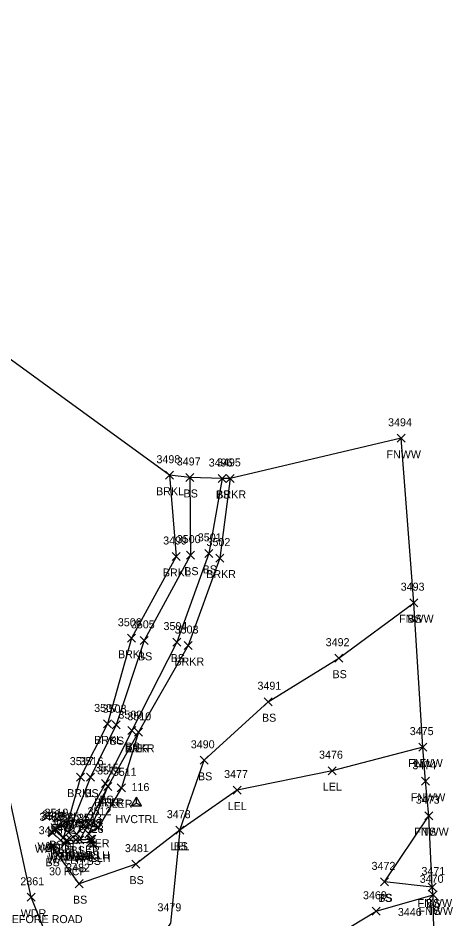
# Model space of a CAD drawing. Extents: x 1650221 to 1650634, y 244606 to 249996.
# Drawn here: x 1650356.4 to 1650465, y 246819.2 to 247044.4 of the extents above; entities that cross this region are included whole.
import ezdxf

# ---------------------------------------------------------------- set-up
doc = ezdxf.new("R2010")
doc.units = 0
for name, color, linetype in [('C_A', 7, 'Continuous'), ('C_I', 7, 'Continuous'), ('CPSM', 7, 'Continuous'), ('D_A', 7, 'Continuous'), ('D_C', 7, 'Continuous'), ('D_I', 7, 'Continuous'), ('D_TIC', 7, 'Continuous'), ('DHW', 7, 'Continuous'), ('L_A', 7, 'Continuous'), ('L_I', 7, 'Continuous'), ('L_TIC', 7, 'Continuous'), ('LARO', 7, 'Continuous'), ('LAWA', 7, 'Continuous'), ('LAWE', 7, 'Continuous'), ('LELB', 7, 'Continuous'), ('LFNC', 7, 'Continuous'), ('LSOGP', 7, 'Continuous'), ('S_C', 7, 'Continuous')]:
    doc.layers.add(name, color=color, linetype=linetype)

msp = doc.modelspace()

# ---------------------------------------------------------------- linework, layer by layer
at = {"layer": 'CPSM'}
for p, q in [((1650384.74, 246847.47), (1650385.99, 246849.64)), ((1650387.24, 246847.47), (1650385.99, 246849.64)), ((1650385.99, 246848.19), (1650385.99, 246849.64)), ((1650384.74, 246847.47), (1650385.99, 246848.19)), ((1650384.74, 246847.47), (1650387.24, 246847.47)), ((1650385.99, 246848.19), (1650385.99, 246848.19)), ((1650385.99, 246848.19), (1650387.24, 246847.47))]:
    msp.add_line(p, q, dxfattribs=at)
at = {"layer": 'D_TIC'}
for points in [[(1650363.97, 246839.77), (1650365.97, 246841.77)], [(1650365.97, 246839.77), (1650363.97, 246841.77)], [(1650364.66, 246840.35), (1650366.66, 246842.35)], [(1650366.66, 246840.35), (1650364.66, 246842.35)], [(1650364.66, 246840.35), (1650366.66, 246842.35)], [(1650366.66, 246840.35), (1650364.66, 246842.35)], [(1650368.48, 246838.15), (1650370.48, 246840.15)], [(1650370.48, 246838.15), (1650368.48, 246840.15)], [(1650373.5, 246838.15), (1650375.5, 246840.15)], [(1650375.5, 246838.15), (1650373.5, 246840.15)], [(1650367.03, 246837.03), (1650369.03, 246839.03)], [(1650369.03, 246837.03), (1650367.03, 246839.03)], [(1650367.35, 246837.78), (1650369.35, 246839.78)], [(1650369.35, 246837.78), (1650367.35, 246839.78)], [(1650367.35, 246837.78), (1650369.35, 246839.78)], [(1650369.35, 246837.78), (1650367.35, 246839.78)], [(1650373.65, 246837.49), (1650375.65, 246839.49)], [(1650375.65, 246837.49), (1650373.65, 246839.49)]]:
    msp.add_lwpolyline(points, dxfattribs=at)
at = {"layer": 'DHW'}
for points in [[(1650365.66, 246841.35), (1650364.97, 246840.77), (1650368.03, 246838.03), (1650374.65, 246838.49), (1650374.5, 246839.15), (1650368.35, 246838.78)], [(1650365.66, 246841.35), (1650368.35, 246838.78)]]:
    msp.add_lwpolyline(points, dxfattribs=at)
at = {"layer": 'L_TIC'}
for points in [[(1650451.05, 246938.34), (1650453.05, 246940.34)], [(1650453.05, 246938.34), (1650451.05, 246940.34)], [(1650393.2, 246929.11), (1650395.2, 246931.11)], [(1650395.2, 246929.11), (1650393.2, 246931.11)], [(1650398.27, 246928.56), (1650400.27, 246930.56)], [(1650400.27, 246928.56), (1650398.27, 246930.56)], [(1650406.32, 246928.28), (1650408.32, 246930.28)], [(1650408.32, 246928.28), (1650406.32, 246930.28)], [(1650408.31, 246928.32), (1650410.31, 246930.32)], [(1650410.31, 246928.32), (1650408.31, 246930.32)], [(1650394.89, 246908.81), (1650396.89, 246910.81)], [(1650396.89, 246908.81), (1650394.89, 246910.81)], [(1650398.44, 246909.15), (1650400.44, 246911.15)], [(1650400.44, 246909.15), (1650398.44, 246911.15)], [(1650403.04, 246909.59), (1650405.04, 246911.59)], [(1650405.04, 246909.59), (1650403.04, 246911.59)], [(1650405.78, 246908.41), (1650407.78, 246910.41)], [(1650407.78, 246908.41), (1650405.78, 246910.41)], [(1650454.2, 246897.26), (1650456.2, 246899.26)], [(1650456.2, 246897.26), (1650454.2, 246899.26)], [(1650454.2, 246897.26), (1650456.2, 246899.26)], [(1650456.2, 246897.26), (1650454.2, 246899.26)], [(1650383.69, 246888.38), (1650385.69, 246890.38)], [(1650385.69, 246888.38), (1650383.69, 246890.38)], [(1650386.89, 246887.85), (1650388.89, 246889.85)], [(1650388.89, 246887.85), (1650386.89, 246889.85)], [(1650395.04, 246887.42), (1650397.04, 246889.42)], [(1650397.04, 246887.42), (1650395.04, 246889.42)], [(1650397.83, 246886.56), (1650399.83, 246888.56)], [(1650399.83, 246886.56), (1650397.83, 246888.56)], [(1650435.47, 246883.4), (1650437.47, 246885.4)], [(1650437.47, 246883.4), (1650435.47, 246885.4)], [(1650417.86, 246872.52), (1650419.86, 246874.52)], [(1650419.86, 246872.52), (1650417.86, 246874.52)], [(1650377.72, 246866.97), (1650379.72, 246868.97)], [(1650379.72, 246866.97), (1650377.72, 246868.97)], [(1650379.85, 246866.77), (1650381.85, 246868.77)], [(1650381.85, 246866.77), (1650379.85, 246868.77)], [(1650383.78, 246865.3), (1650385.78, 246867.3)], [(1650385.78, 246865.3), (1650383.78, 246867.3)], [(1650385.45, 246864.88), (1650387.45, 246866.88)], [(1650387.45, 246864.88), (1650385.45, 246866.88)], [(1650385.45, 246864.88), (1650387.45, 246866.88)], [(1650387.45, 246864.88), (1650385.45, 246866.88)], [(1650456.47, 246861.18), (1650458.47, 246863.18)], [(1650458.47, 246861.18), (1650456.47, 246863.18)], [(1650456.47, 246861.18), (1650458.47, 246863.18)], [(1650458.47, 246861.18), (1650456.47, 246863.18)], [(1650401.87, 246857.88), (1650403.87, 246859.88)], [(1650403.87, 246857.88), (1650401.87, 246859.88)], [(1650433.86, 246855.29), (1650435.86, 246857.29)], [(1650435.86, 246855.29), (1650433.86, 246857.29)], [(1650370.99, 246853.68), (1650372.99, 246855.68)], [(1650372.99, 246853.68), (1650370.99, 246855.68)], [(1650373.49, 246853.67), (1650375.49, 246855.67)], [(1650375.49, 246853.67), (1650373.49, 246855.67)], [(1650377.24, 246852.05), (1650379.24, 246854.05)], [(1650379.24, 246852.05), (1650377.24, 246854.05)], [(1650457.12, 246852.65), (1650459.12, 246854.65)], [(1650459.12, 246852.65), (1650457.12, 246854.65)], [(1650377.8, 246851.35), (1650379.8, 246853.35)], [(1650379.8, 246851.35), (1650377.8, 246853.35)], [(1650377.8, 246851.35), (1650379.8, 246853.35)], [(1650379.8, 246851.35), (1650377.8, 246853.35)], [(1650381.17, 246851.01), (1650383.17, 246853.01)], [(1650383.17, 246851.01), (1650381.17, 246853.01)], [(1650410.1, 246850.45), (1650412.1, 246852.45)], [(1650412.1, 246850.45), (1650410.1, 246852.45)], [(1650457.97, 246844.05), (1650459.97, 246846.05)], [(1650459.97, 246844.05), (1650457.97, 246846.05)], [(1650457.97, 246844.05), (1650459.97, 246846.05)], [(1650459.97, 246844.05), (1650457.97, 246846.05)], [(1650364.7, 246840.8), (1650366.7, 246842.8)], [(1650366.7, 246840.8), (1650364.7, 246842.8)], [(1650375.43, 246841.16), (1650377.43, 246843.16)], [(1650377.43, 246841.16), (1650375.43, 246843.16)], [(1650395.79, 246840.42), (1650397.79, 246842.42)], [(1650397.79, 246840.42), (1650395.79, 246842.42)], [(1650395.79, 246840.42), (1650397.79, 246842.42)], [(1650397.79, 246840.42), (1650395.79, 246842.42)], [(1650395.79, 246840.42), (1650397.79, 246842.42)], [(1650397.79, 246840.42), (1650395.79, 246842.42)], [(1650363.79, 246839.99), (1650365.79, 246841.99)], [(1650365.79, 246839.99), (1650363.79, 246841.99)], [(1650366.76, 246838.63), (1650368.76, 246840.63)], [(1650368.76, 246838.63), (1650366.76, 246840.63)], [(1650366.76, 246838.63), (1650368.76, 246840.63)], [(1650368.76, 246838.63), (1650366.76, 246840.63)], [(1650367.96, 246839.82), (1650369.96, 246841.82)], [(1650369.96, 246839.82), (1650367.96, 246841.82)], [(1650367.96, 246839.82), (1650369.96, 246841.82)], [(1650369.96, 246839.82), (1650367.96, 246841.82)], [(1650370.07, 246839.39), (1650372.07, 246841.39)], [(1650372.07, 246839.39), (1650370.07, 246841.39)], [(1650373.03, 246839.52), (1650375.03, 246841.52)], [(1650375.03, 246839.52), (1650373.03, 246841.52)], [(1650373.76, 246838.22), (1650375.76, 246840.22)], [(1650375.76, 246838.22), (1650373.76, 246840.22)], [(1650363.79, 246836.41), (1650365.79, 246838.41)], [(1650365.79, 246836.41), (1650363.79, 246838.41)], [(1650367.55, 246837.93), (1650369.55, 246839.93)], [(1650369.55, 246837.93), (1650367.55, 246839.93)], [(1650369.81, 246838.01), (1650371.81, 246840.01)], [(1650371.81, 246838.01), (1650369.81, 246840.01)], [(1650370.78, 246838.01), (1650372.78, 246840.01)], [(1650372.78, 246838.01), (1650370.78, 246840.01)], [(1650370.78, 246838.01), (1650372.78, 246840.01)], [(1650372.78, 246838.01), (1650370.78, 246840.01)], [(1650374.06, 246836.75), (1650376.06, 246838.75)], [(1650376.06, 246836.75), (1650374.06, 246838.75)], [(1650384.76, 246831.94), (1650386.76, 246833.94)], [(1650386.76, 246831.94), (1650384.76, 246833.94)], [(1650370.64, 246827.06), (1650372.64, 246829.06)], [(1650372.64, 246827.06), (1650370.64, 246829.06)], [(1650446.92, 246827.51), (1650448.92, 246829.51)], [(1650448.92, 246827.51), (1650446.92, 246829.51)], [(1650446.92, 246827.51), (1650448.92, 246829.51)], [(1650448.92, 246827.51), (1650446.92, 246829.51)], [(1650458.82, 246826.21), (1650460.82, 246828.21)], [(1650460.82, 246826.21), (1650458.82, 246828.21)], [(1650458.82, 246826.21), (1650460.82, 246828.21)], [(1650460.82, 246826.21), (1650458.82, 246828.21)], [(1650358.68, 246823.66), (1650360.68, 246825.66)], [(1650360.68, 246823.66), (1650358.68, 246825.66)], [(1650459.05, 246824.27), (1650461.05, 246826.27)], [(1650461.05, 246824.27), (1650459.05, 246826.27)], [(1650459.05, 246824.27), (1650461.05, 246826.27)], [(1650461.05, 246824.27), (1650459.05, 246826.27)], [(1650444.83, 246820.17), (1650446.83, 246822.17)], [(1650446.83, 246820.17), (1650444.83, 246822.17)]]:
    msp.add_lwpolyline(points, dxfattribs=at)
at = {"layer": 'LARO'}
for points in [[(1650386.45, 246865.88), (1650382.17, 246852.01), (1650376.43, 246842.16), (1650374.03, 246840.52), (1650378.8, 246852.35)], [(1650457.47, 246862.18), (1650434.86, 246856.29), (1650411.1, 246851.45), (1650396.79, 246841.42), (1650394.47, 246818.16), (1650381.73, 246799.85)]]:
    msp.add_lwpolyline(points, dxfattribs=at)
at = {"layer": 'LAWA'}
msp.add_lwpolyline([(1650378.2, 246794.91), (1650374.9, 246794.97), (1650368.73, 246802.01), (1650359.68, 246824.66), (1650349.32, 246871.74), (1650348.02, 246917.21), (1650345.5, 246965.53), (1650341.28, 247016.15), (1650338.12, 247059.96), (1650335.1, 247106.89), (1650329.41, 247153.66), (1650323.25, 247198.71), (1650318.64, 247242.09)], dxfattribs=at)
at = {"layer": 'LAWE'}
for points in [[(1650394.2, 246930.11), (1650395.89, 246909.81), (1650384.69, 246889.38), (1650378.72, 246867.97), (1650371.99, 246854.68), (1650367.76, 246839.63)], [(1650409.31, 246929.32), (1650406.78, 246909.41), (1650398.83, 246887.56), (1650386.45, 246865.88), (1650378.8, 246852.35), (1650371.78, 246839.01)]]:
    msp.add_lwpolyline(points, dxfattribs=at)
at = {"layer": 'LELB'}
for points in [[(1650399.27, 246929.56), (1650399.44, 246910.15), (1650387.89, 246888.85), (1650380.85, 246867.77), (1650374.49, 246854.67), (1650368.96, 246840.82)], [(1650407.32, 246929.28), (1650404.04, 246910.59), (1650396.04, 246888.42), (1650384.78, 246866.3), (1650378.24, 246853.05), (1650371.07, 246840.39), (1650368.96, 246840.82)], [(1650396.79, 246841.42), (1650402.87, 246858.88), (1650418.86, 246873.52), (1650436.47, 246884.4), (1650455.2, 246898.26)], [(1650447.92, 246828.51), (1650458.97, 246845.05)], [(1650364.79, 246840.99), (1650365.7, 246841.8), (1650367.76, 246839.63), (1650368.55, 246838.93), (1650370.81, 246839.01), (1650371.78, 246839.01), (1650374.76, 246839.22), (1650375.06, 246837.75)], [(1650396.79, 246841.42), (1650385.76, 246832.94), (1650371.64, 246828.06), (1650364.79, 246837.41)], [(1650459.82, 246827.21), (1650447.92, 246828.51)], [(1650397.68, 246807.37), (1650415.94, 246813.19), (1650432.77, 246813.27), (1650445.83, 246821.17), (1650460.05, 246825.27)]]:
    msp.add_lwpolyline(points, dxfattribs=at)
at = {"layer": 'LFNC'}
msp.add_lwpolyline([(1650460.29, 246812.05), (1650460.05, 246825.27), (1650459.82, 246827.21), (1650458.97, 246845.05), (1650458.12, 246853.65), (1650457.47, 246862.18), (1650455.2, 246898.26), (1650452.05, 246939.34)], dxfattribs=at)
at = {"layer": 'LSOGP'}
msp.add_lwpolyline([(1650460.29, 246812.05), (1650460.05, 246825.27), (1650459.82, 246827.21), (1650458.97, 246845.05), (1650458.12, 246853.65), (1650457.47, 246862.18), (1650455.2, 246898.26), (1650452.05, 246939.34), (1650409.31, 246929.32), (1650407.32, 246929.28), (1650399.27, 246929.56), (1650394.2, 246930.11), (1650345.5, 246965.53), (1650341.28, 247016.15), (1650338.12, 247059.96)], dxfattribs=at)

# ---------------------------------------------------------------- texts
at = {"layer": 'C_A'}
msp.add_text('HVCTRL', height=2, dxfattribs=at).set_placement((1650380.69, 246843.19))
at = {"layer": 'C_I'}
msp.add_text('116', height=2, dxfattribs=at).set_placement((1650384.71, 246851.19))
at = {"layer": 'D_A'}
for s, p in [('WALLH', (1650361.25, 246836.35)), ('WALLH', (1650361.25, 246836.35)), ('WALLH', (1650360.56, 246835.77)), ('WALLH', (1650363.94, 246833.78)), ('WALLH', (1650363.94, 246833.78)), ('P', (1650368.86, 246834.15)), ('WALLH', (1650370.09, 246834.15)), ('WALLH', (1650363.62, 246833.03)), ('WALLH', (1650370.24, 246833.49))]:
    msp.add_text(s, height=2, dxfattribs=at).set_placement(p)
at = {"layer": 'D_C'}
msp.add_text('30 RCP', height=2, dxfattribs=at).set_placement((1650364.12, 246830.15))
at = {"layer": 'D_I'}
for s, p in [('3485', (1650361.71, 246843.77)), ('3484', (1650362.4, 246844.35)), ('3484', (1650362.4, 246844.35)), ('3486', (1650364.71, 246841.03)), ('3489', (1650365.08, 246841.78)), ('3489', (1650365.08, 246841.78)), ('3526', (1650366.16, 246842.15)), ('3488', (1650371.24, 246842.15)), ('3487', (1650371.39, 246841.49))]:
    msp.add_text(s, height=2, dxfattribs=at).set_placement(p)
at = {"layer": 'L_A'}
for s, p in [('FNWW', (1650448.39, 246934.34)), ('BRKL', (1650390.85, 246925.11)), ('BS', (1650397.71, 246924.56)), ('BS', (1650405.76, 246924.28)), ('BRKR', (1650405.9, 246924.32)), ('BRKL', (1650392.53, 246904.81)), ('BS', (1650397.88, 246905.15)), ('BS', (1650402.48, 246905.59)), ('BRKR', (1650403.37, 246904.41)), ('FNWW', (1650451.55, 246893.26)), ('BS', (1650453.64, 246893.26)), ('BRKL', (1650381.34, 246884.38)), ('BS', (1650386.33, 246883.85)), ('BS', (1650394.48, 246883.42)), ('BRKR', (1650395.42, 246882.56)), ('BS', (1650434.91, 246879.4)), ('BS', (1650417.3, 246868.52)), ('BRKL', (1650375.37, 246862.97)), ('BS', (1650379.29, 246862.77)), ('BRKR', (1650383.04, 246860.88)), ('BS', (1650383.23, 246861.3)), ('LER', (1650384.03, 246860.88)), ('FNWW', (1650453.82, 246857.18)), ('LEL', (1650455.11, 246857.18)), ('BS', (1650401.31, 246853.88)), ('BRKL', (1650368.64, 246849.68)), ('BS', (1650372.94, 246849.67)), ('LEL', (1650432.5, 246851.29)), ('BRKR', (1650375.39, 246847.35)), ('LER', (1650376.38, 246847.35)), ('BS', (1650376.68, 246848.05)), ('FNWW', (1650454.47, 246848.65)), ('LER', (1650379.75, 246847.01)), ('LEL', (1650408.74, 246846.45)), ('FNWW', (1650455.32, 246840.05)), ('TS', (1650457.38, 246840.05)), ('BS', (1650363.23, 246835.99)), ('BS', (1650364.14, 246836.8)), ('LER', (1650374.02, 246837.16)), ('LEL', (1650394.43, 246836.42)), ('BS', (1650395.23, 246836.42)), ('BS', (1650395.23, 246836.42)), ('BRKL', (1650364.41, 246834.63)), ('BS', (1650366.2, 246834.63)), ('BS', (1650367, 246833.93)), ('BS', (1650367.4, 246835.82)), ('BS', (1650367.4, 246835.82)), ('BRKR', (1650368.37, 246834.01)), ('BS', (1650369.25, 246834.01)), ('BS', (1650369.51, 246835.39)), ('BS', (1650370.22, 246834.01)), ('LER', (1650371.61, 246835.52)), ('BS', (1650373.2, 246834.22)), ('BS', (1650363.23, 246832.41)), ('BS', (1650373.5, 246832.75)), ('BS', (1650384.2, 246827.94)), ('BS', (1650370.09, 246823.06)), ('TS', (1650446.33, 246823.51)), ('BS', (1650446.36, 246823.51)), ('FNWW', (1650456.16, 246822.21)), ('FNWW', (1650456.39, 246820.27)), ('BS', (1650458.26, 246822.21)), ('TS', (1650458.46, 246820.27)), ('WDR', (1650357.05, 246819.66))]:
    msp.add_text(s, height=2, dxfattribs=at).set_placement(p)
at = {"layer": 'L_I'}
for s, p in [('3494', (1650448.79, 246942.34)), ('3498', (1650390.94, 246933.11)), ('3497', (1650396.01, 246932.56)), ('3496', (1650404, 246932.28)), ('3495', (1650406.05, 246932.32)), ('3499', (1650392.62, 246912.81)), ('3500', (1650396.02, 246913.15)), ('3501', (1650401.27, 246913.59)), ('3502', (1650403.44, 246912.41)), ('3493', (1650451.94, 246901.26)), ('3493', (1650451.94, 246901.26)), ('3506', (1650381.3, 246892.38)), ('3505', (1650384.55, 246891.85)), ('3504', (1650392.7, 246891.42)), ('3503', (1650395.49, 246890.56)), ('3492', (1650433.21, 246887.4)), ('3491', (1650416.17, 246876.52)), ('3507', (1650375.38, 246870.97)), ('3508', (1650377.51, 246870.77)), ('3509', (1650381.44, 246869.3)), ('3510', (1650383.67, 246868.88)), ('3510', (1650383.67, 246868.88)), ('3475', (1650454.21, 246865.18)), ('3475', (1650454.21, 246865.18)), ('3490', (1650399.52, 246861.88)), ('3476', (1650431.55, 246859.29)), ('3517', (1650369.3, 246857.68)), ('3516', (1650371.75, 246857.67)), ('3474', (1650454.86, 246856.65)), ('3515', (1650375.55, 246856.05)), ('3514', (1650376.11, 246855.35)), ('3514', (1650376.11, 246855.35)), ('3511', (1650380.04, 246855.01)), ('3477', (1650407.84, 246854.45)), ('3473', (1650455.71, 246848.05)), ('3473', (1650455.71, 246848.05)), ('3512', (1650373.74, 246845.16)), ('3518', (1650362.09, 246843.99)), ('3519', (1650363, 246844.8)), ('3520', (1650364.42, 246842.63)), ('3520', (1650364.42, 246842.63)), ('3525', (1650365.7, 246843.82)), ('3525', (1650365.7, 246843.82)), ('3524', (1650367.81, 246843.39)), ('3513', (1650371.34, 246843.52)), ('3478', (1650393.53, 246844.42)), ('3478', (1650393.53, 246844.42)), ('3478', (1650393.53, 246844.42)), ('3483', (1650361.53, 246840.41)), ('3521', (1650365.86, 246841.93)), ('3522', (1650367.55, 246842.01)), ('3523', (1650368.52, 246842.01)), ('3523', (1650368.52, 246842.01)), ('3527', (1650371.5, 246842.22)), ('3528', (1650371.8, 246840.75)), ('3481', (1650383.07, 246835.94)), ('3472', (1650444.66, 246831.51)), ('3472', (1650444.66, 246831.51)), ('3482', (1650368.38, 246831.06)), ('3471', (1650457.12, 246830.21)), ('3471', (1650457.12, 246830.21)), ('2361', (1650356.94, 246827.66)), ('3470', (1650456.7, 246828.27)), ('3470', (1650456.7, 246828.27)), ('3469', (1650442.52, 246824.17)), ('3479', (1650391.2, 246821.16)), ('3446', (1650451.24, 246819.97))]:
    msp.add_text(s, height=2, dxfattribs=at).set_placement(p)
at = {"layer": 'S_C'}
msp.add_text('BRIDGES FREEZE BEFORE ROAD', height=2, dxfattribs=at).set_placement((1650328.95, 246818.21))

doc.saveas('drawing.dxf')
